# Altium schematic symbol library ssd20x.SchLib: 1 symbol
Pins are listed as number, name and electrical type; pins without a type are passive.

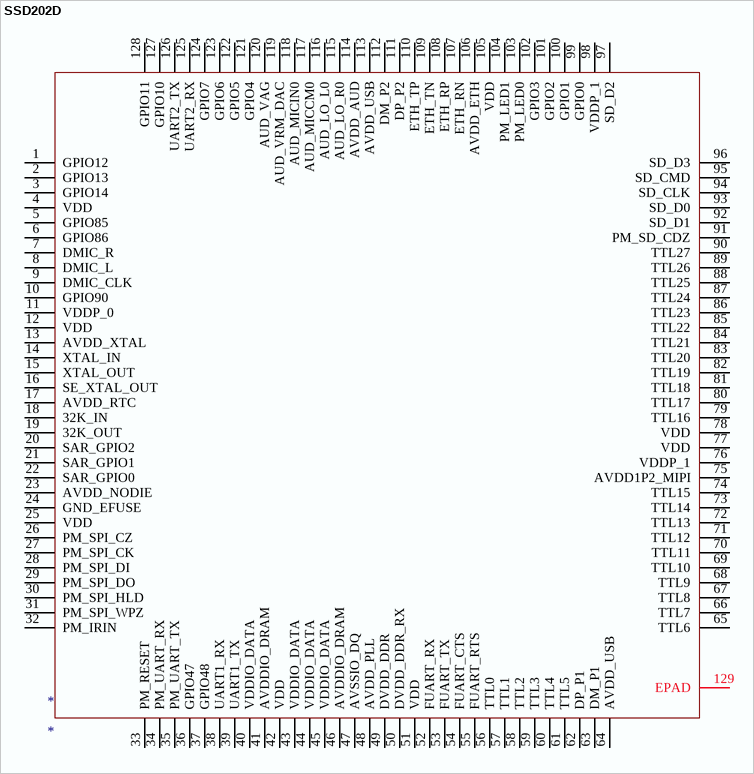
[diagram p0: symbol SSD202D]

## SSD202D
designator *
footprint QFN35P1230X1230X90-128N (QFN, 128-Leads, Body 12.4x12.4mm (max), Pitch 0.35mm, IPC Medium Density)
pins: 1 GPIO12, 2 GPIO13, 3 GPIO14, 4 VDD, 5 GPIO85, 6 GPIO86, 7 DMIC_R, 8 DMIC_L, 9 DMIC_CLK, 10 GPIO90, 11 VDDP_0, 12 VDD, 13 AVDD_XTAL, 14 XTAL_IN, 15 XTAL_OUT, 16 SE_XTAL_OUT, 17 AVDD_RTC, 18 32K_IN, 19 32K_OUT, 20 SAR_GPIO2, 21 SAR_GPIO1, 22 SAR_GPIO0, 23 AVDD_NODIE, 24 GND_EFUSE, 25 VDD, 26 PM_SPI_CZ, 27 PM_SPI_CK, 28 PM_SPI_DI, 29 PM_SPI_DO, 30 PM_SPI_HLD, 31 PM_SPI_WPZ, 32 PM_IRIN, 33 PM_RESET, 34 PM_UART_RX, 35 PM_UART_TX, 36 GPIO47, 37 GPIO48, 38 UART1_RX, 39 UART1_TX, 40 VDDIO_DATA, 41 AVDDIO_DRAM, 42 VDD, 43 VDDIO_DATA, 44 VDDIO_DATA, 45 VDDIO_DATA, 46 AVDDIO_DRAM, 47 AVSSIO_DQ, 48 AVDD_PLL, 49 DVDD_DDR, 50 DVDD_DDR_RX, 51 VDD, 52 FUART_RX, 53 FUART_TX, 54 FUART_CTS, 55 FUART_RTS, 56 TTL0, 57 TTL1, 58 TTL2, 59 TTL3, 60 TTL4, 61 TTL5, 62 DP_P1, 63 DM_P1, 64 AVDD_USB, 65 TTL6, 66 TTL7, 67 TTL8, 68 TTL9, 69 TTL10, 70 TTL11, 71 TTL12, 72 TTL13, 73 TTL14, 74 TTL15, 75 AVDD1P2_MIPI, 76 VDDP_1, 77 VDD, 78 VDD, 79 TTL16, 80 TTL17, 81 TTL18, 82 TTL19, 83 TTL20, 84 TTL21, 85 TTL22, 86 TTL23, 87 TTL24, 88 TTL25, 89 TTL26, 90 TTL27, 91 PM_SD_CDZ, 92 SD_D1, 93 SD_D0, 94 SD_CLK, 95 SD_CMD, 96 SD_D3, 97 SD_D2, 98 VDDP_1, 99 GPIO0, 100 GPIO1, 101 GPIO2, 102 GPIO3, 103 PM_LED0, 104 PM_LED1, 105 VDD, 106 AVDD_ETH, 107 ETH_RN, 108 ETH_RP, 109 ETH_TN, 110 ETH_TP, 111 DP_P2, 112 DM_P2, 113 AVDD_USB, 114 AVDD_AUD, 115 AUD_LO_R0, 116 AUD_LO_L0, 117 AUD_MICCM0, 118 AUD_MICIN0, 119 AUD_VRM_DAC, 120 AUD_VAG, 121 GPIO4, 122 GPIO5, 123 GPIO6, 124 GPIO7, 125 UART2_RX, 126 UART2_TX, 127 GPIO10, 128 GPIO11, 129 EPAD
